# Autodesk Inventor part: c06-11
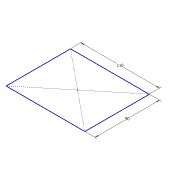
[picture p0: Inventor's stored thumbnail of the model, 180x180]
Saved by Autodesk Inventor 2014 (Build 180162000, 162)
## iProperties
Created: 2013-03
Part Number: c06-11
Material: Generic
Document SubType Name: Modeling
Designer: Thom Tremblay
Density: 1 g/cm^3
Appearance: Chrome - Polished Blue
Author: Thom Tremblay
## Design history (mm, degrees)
sketch "Sketch1"
  geometry: L1 (-55, -45)-(55, -45); L2 (55, -45)-(55, 45); L3 (55, 45)-(-55, 45); L4 (-55, 45)-(-55, -45); L5 (-55, -45)-(55, 45); L6 (55, -45)-(-55, 45); 1 further point
  constraints: 12 end point, 2 midpoint, 2 parallel, 1 horizontal, 1 perpendicular
  dimensions: "d0" = 110 distance of L3.end L2.end; "d1" = 90 distance of L2.end L1.end
sketch "Sketch2"
  geometry: L1 (0, -20)-(70, -20); L2 (70, 20)-(0, 20); L3 (0, 20)-(0, -20); A1 r 20 centre (70, 0) between (70, -20) and (70, 20); 2 further points
  constraints: 6 end point, 2 point on circle, 1 centre point, 1 coincident, 1 horizontal, 1 midpoint, 1 parallel
  dimensions: "d4" = 90 dimension on A1 L3; "d5" = 20 radius of A1
